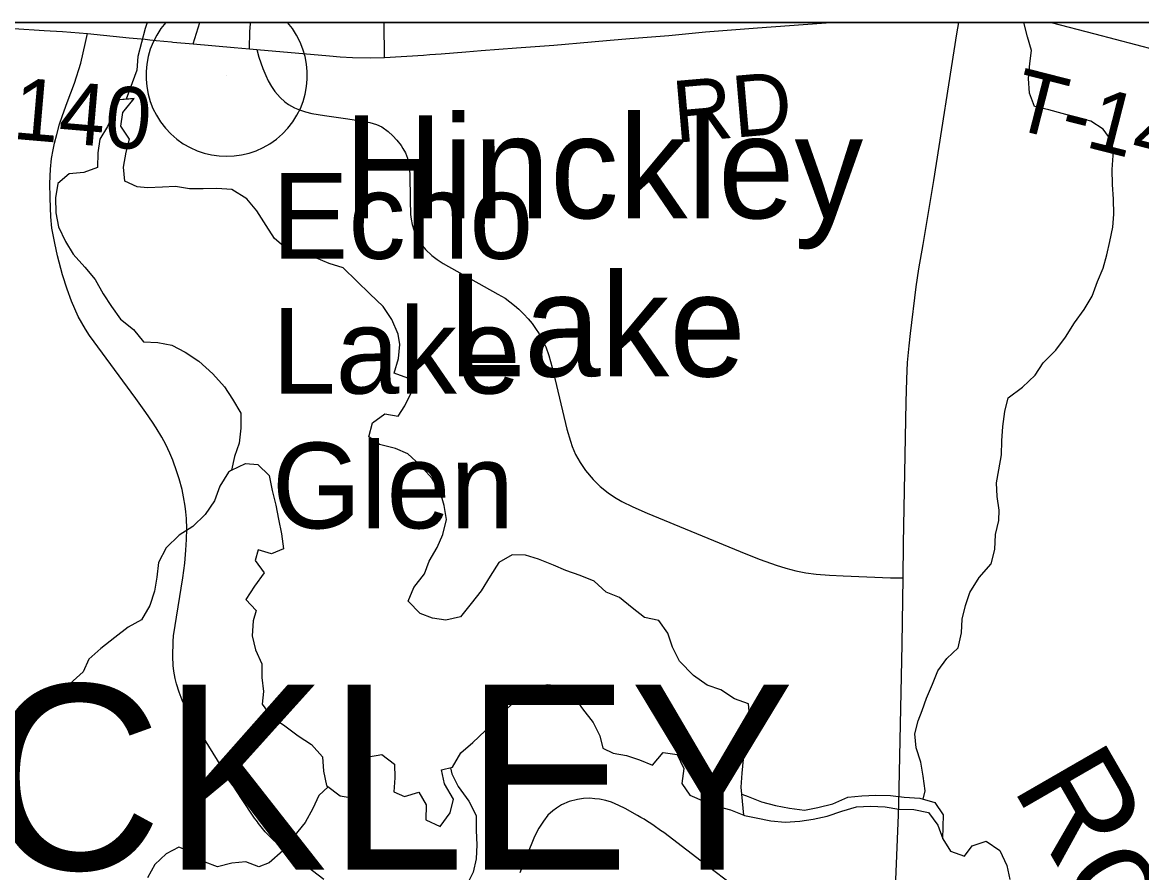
# Model space of a CAD drawing. Extents: x 0 to 34, y 0 to 22.
# Drawn here: x 6.095 to 7.127, y 20.117 to 20.9 of the extents above; entities that cross this region are included whole.
import ezdxf

# ---------------------------------------------------------------- set-up
doc = ezdxf.new("R2010")
doc.units = 0
for name, color, linetype in [('GM_X_Corporation', 7, 'Continuous'), ('GM_X_County_Road', 7, 'Continuous'), ('GM_X_County_Road_Text', 7, 'Continuous'), ('GM_X_Major_Lake', 7, 'Continuous'), ('GM_X_Major_Lake_Text', 7, 'Continuous'), ('GM_X_Minor_River', 7, 'Continuous'), ('GM_X_Minor_River_Text', 7, 'Continuous'), ('GM_X_State_Shield', 7, 'Continuous'), ('GM_X_Township_Road', 7, 'Continuous'), ('GM_X_Township_Road_Text', 7, 'Continuous'), ('GM_X_Township_Text', 7, 'Continuous'), ('GM_X_Unincorporated_Location', 7, 'Continuous'), ('GM_X_Unincorporated_Text', 7, 'Continuous'), ('SH_Data', 7, 'Continuous')]:
    doc.layers.add(name, color=color, linetype=linetype)

msp = doc.modelspace()

# ---------------------------------------------------------------- linework, layer by layer
at = {"layer": 'GM_X_Corporation'}
msp.add_lwpolyline([(7.991, 17.7727), (7.9901, 18.1613), (7.988, 19.001), (7.9884, 19.0254), (7.9898, 19.1149), (7.9901, 19.6615), (7.9904, 20.2824), (7.9906, 20.6512), (7.9922, 20.9), (2.1, 20.9), (2.1, 14.1)], dxfattribs=at)
msp.add_lwpolyline([(7.9922, 20.9), (2.8099, 20.9), (2.8107, 20.774), (2.8158, 19.9868), (2.8247, 19.0323), (3.279, 19.0395), (3.3208, 19.0402), (3.8964, 19.0508), (4.1999, 19.0575), (4.5008, 19.0629), (4.7704, 19.0672), (4.9094, 19.0728), (5.4081, 19.0763), (6.7986, 19.0964), (7.9898, 19.1149), (7.9901, 19.6615), (7.9904, 20.2824), (7.9906, 20.6512)], close=True, dxfattribs=at)
at = {"layer": 'GM_X_County_Road'}
for points in [[(5.9874, 20.8999), (6.0214, 20.8978), (6.0292, 20.8975), (6.0736, 20.8949), (6.0871, 20.8943), (6.1153, 20.8926), (6.1321, 20.8917), (6.155, 20.8899), (6.1936, 20.8859)], [(6.2326, 20.882), (6.2337, 20.8819), (6.2524, 20.8803), (6.2902, 20.8768), (6.3044, 20.8756), (6.3111, 20.8749), (6.3781, 20.8691), (6.3879, 20.8684), (6.3995, 20.8678), (6.416, 20.8674), (6.429, 20.8677), (6.4649, 20.8699), (6.4707, 20.8703), (6.4811, 20.871), (6.5039, 20.873), (6.5179, 20.8741), (6.5507, 20.8766), (6.585, 20.8789), (6.6197, 20.8821), (6.6369, 20.8836), (6.6552, 20.8851), (6.6709, 20.8864), (6.691, 20.888), (6.7248, 20.8912), (6.7729, 20.8949), (6.8318, 20.8993), (6.8403, 20.9)], [(6.9003, 20.1099), (6.9027, 20.1697), (6.9031, 20.1793), (6.9062, 20.3272), (6.907, 20.3883), (6.9073, 20.4197), (6.9097, 20.55), (6.9103, 20.5711), (6.911, 20.5866), (6.9125, 20.6021), (6.9138, 20.6133), (6.9191, 20.6562), (6.9216, 20.673), (6.9254, 20.6953), (6.9352, 20.7542), (6.9566, 20.8895), (6.9584, 20.9)], [(6.1936, 20.8859), (6.2084, 20.8844), (6.2125, 20.884), (6.2184, 20.8834), (6.2326, 20.882)]]:
    msp.add_lwpolyline(points, dxfattribs=at)
at = {"layer": 'GM_X_Major_Lake'}
for points in [[(6.1981, 20.8298), (6.1842, 20.8287), (6.1793, 20.8162), (6.1737, 20.804), (6.1665, 20.7925), (6.1647, 20.7799), (6.1644, 20.7662), (6.1518, 20.7616), (6.1381, 20.7604), (6.1279, 20.7516), (6.1257, 20.7383), (6.1258, 20.7246), (6.1285, 20.7117), (6.1347, 20.698), (6.1419, 20.6863), (6.1527, 20.6745), (6.1622, 20.6632), (6.1695, 20.6499), (6.1772, 20.6381), (6.1856, 20.6264), (6.1975, 20.6169), (6.2067, 20.6056), (6.22, 20.6049), (6.2329, 20.6026), (6.2451, 20.5962), (6.2577, 20.5879), (6.2707, 20.5762), (6.2814, 20.5641), (6.2887, 20.5527), (6.2964, 20.5398), (6.2965, 20.5261), (6.295, 20.5124), (6.2905, 20.4999), (6.2879, 20.4873), (6.3008, 20.4934), (6.3122, 20.4927), (6.3226, 20.4825), (6.3253, 20.4688), (6.3288, 20.4552), (6.3311, 20.4422), (6.3339, 20.4286), (6.3359, 20.4149), (6.3248, 20.4103), (6.3126, 20.414), (6.3097, 20.4041), (6.3181, 20.3927), (6.309, 20.3805), (6.3011, 20.3683), (6.3106, 20.3581), (6.3077, 20.3486), (6.307, 20.3349), (6.3101, 20.3219), (6.3158, 20.309), (6.3159, 20.2965), (6.3175, 20.2836), (6.316, 20.2718), (6.3245, 20.2604), (6.3371, 20.2517), (6.3493, 20.2426), (6.3615, 20.2347), (6.3718, 20.2234), (6.3727, 20.21), (6.3754, 20.1967), (6.388, 20.1873), (6.4013, 20.1851), (6.4035, 20.1988), (6.4046, 20.2125), (6.4141, 20.2232), (6.4266, 20.2255), (6.4381, 20.2165), (6.4385, 20.2039), (6.4374, 20.191), (6.4474, 20.1868), (6.4606, 20.1907), (6.4672, 20.1789), (6.4669, 20.1652), (6.4802, 20.1592), (6.4893, 20.1718), (6.4926, 20.1844), (6.4842, 20.1984), (6.4815, 20.2113), (6.4917, 20.2137), (6.4993, 20.227), (6.5103, 20.2366), (6.5216, 20.2473), (6.533, 20.2599), (6.5451, 20.2706), (6.5545, 20.2828), (6.5675, 20.2882), (6.5796, 20.2898), (6.5918, 20.2883), (6.6033, 20.2789), (6.6113, 20.2675), (6.6213, 20.255), (6.6274, 20.2425)], [(6.1977, 20.8297), (6.1842, 20.8287), (6.1793, 20.8162), (6.1737, 20.804), (6.1665, 20.7925), (6.1647, 20.7799), (6.1644, 20.7662), (6.1518, 20.7616), (6.1381, 20.7604), (6.1279, 20.7516), (6.1257, 20.7383), (6.1258, 20.7246), (6.1285, 20.7117), (6.1347, 20.698), (6.1419, 20.6863), (6.1527, 20.6745), (6.1622, 20.6632), (6.1695, 20.6499), (6.1772, 20.6381), (6.1856, 20.6264), (6.1975, 20.6169), (6.2067, 20.6056), (6.22, 20.6049), (6.2329, 20.6026), (6.2451, 20.5962), (6.2577, 20.5879), (6.2707, 20.5762), (6.2814, 20.5641), (6.2887, 20.5527), (6.2964, 20.5398), (6.2965, 20.5261), (6.295, 20.5124), (6.2905, 20.4999), (6.2879, 20.4873), (6.3008, 20.4934), (6.3122, 20.4927), (6.3226, 20.4825), (6.3253, 20.4688), (6.3288, 20.4552), (6.3311, 20.4422), (6.3339, 20.4286), (6.3359, 20.4149), (6.3248, 20.4103), (6.3126, 20.414), (6.3097, 20.4041), (6.3181, 20.3927), (6.309, 20.3805), (6.3011, 20.3683), (6.3106, 20.3581), (6.3077, 20.3486), (6.307, 20.3349), (6.3101, 20.3219), (6.3158, 20.309), (6.3159, 20.2965), (6.3175, 20.2836), (6.316, 20.2718), (6.3245, 20.2604), (6.3371, 20.2517), (6.3493, 20.2426), (6.3615, 20.2347), (6.3718, 20.2234), (6.3727, 20.21), (6.3754, 20.1967), (6.388, 20.1873), (6.4013, 20.1851), (6.4035, 20.1988), (6.4046, 20.2125), (6.4141, 20.2232), (6.4266, 20.2255), (6.4381, 20.2165), (6.4385, 20.2039), (6.4374, 20.191), (6.4474, 20.1868), (6.4606, 20.1907), (6.4672, 20.1789), (6.4669, 20.1652), (6.4802, 20.1592), (6.4893, 20.1718), (6.4926, 20.1844), (6.4842, 20.1984), (6.4815, 20.2113), (6.4917, 20.2137), (6.4993, 20.227), (6.5103, 20.2366), (6.5216, 20.2473), (6.533, 20.2599), (6.5451, 20.2706), (6.5545, 20.2828), (6.5675, 20.2882), (6.5796, 20.2898), (6.5918, 20.2883), (6.6033, 20.2789), (6.6113, 20.2675), (6.6213, 20.255), (6.6274, 20.2425)], [(6.1859, 20.8044), (6.1877, 20.817), (6.1981, 20.8298)], [(6.1859, 20.8044), (6.1877, 20.817), (6.1979, 20.8296)], [(6.6274, 20.2425), (6.6301, 20.2311), (6.6397, 20.2266), (6.6519, 20.2244), (6.6641, 20.2206), (6.6759, 20.2157), (6.6857, 20.2272), (6.6987, 20.2254), (6.7048, 20.2125), (6.703, 20.1988), (6.7103, 20.1878), (6.724, 20.1821), (6.7362, 20.1776), (6.748, 20.1743), (6.7602, 20.1694), (6.759, 20.1823), (6.7578, 20.1952), (6.7585, 20.2082), (6.7599, 20.2211), (6.7595, 20.2336), (6.7617, 20.2466), (6.7658, 20.2588), (6.7646, 20.2721), (6.7517, 20.2766), (6.7391, 20.2849), (6.7265, 20.2894), (6.7139, 20.2981), (6.7009, 20.3113), (6.6944, 20.3242), (6.6901, 20.3371), (6.6817, 20.3489), (6.6687, 20.3515), (6.6573, 20.3606), (6.6454, 20.37), (6.6332, 20.3749), (6.6221, 20.3851), (6.6092, 20.3904), (6.5962, 20.3949), (6.5848, 20.3998), (6.571, 20.4054), (6.5588, 20.4091), (6.5467, 20.4095), (6.5342, 20.4022), (6.5262, 20.3896), (6.5179, 20.3762), (6.5089, 20.3644), (6.499, 20.3522), (6.4853, 20.3491), (6.4732, 20.3509), (6.4617, 20.3554), (6.4506, 20.3668), (6.4559, 20.3793), (6.4657, 20.3919), (6.4702, 20.4034), (6.4774, 20.416), (6.4827, 20.4282), (6.486, 20.4419), (6.484, 20.4548), (6.4802, 20.4677), (6.4729, 20.4798), (6.4618, 20.492), (6.4503, 20.5025), (6.4389, 20.5074), (6.4244, 20.5112), (6.4145, 20.518), (6.4178, 20.5309), (6.4292, 20.5393), (6.4414, 20.5371), (6.4478, 20.5467), (6.4538, 20.5592), (6.4503, 20.5722), (6.4378, 20.5767), (6.4419, 20.5904), (6.443, 20.6033), (6.4414, 20.6128), (6.4356, 20.6261), (6.4276, 20.6382), (6.4153, 20.65), (6.4035, 20.6617), (6.3909, 20.6738), (6.3779, 20.6779), (6.3661, 20.6828), (6.3531, 20.6873), (6.3398, 20.6903), (6.3276, 20.7009), (6.3199, 20.713), (6.3111, 20.7263), (6.3019, 20.7373), (6.2881, 20.7459), (6.2744, 20.747), (6.2619, 20.7466), (6.2493, 20.7465), (6.2364, 20.7487), (6.2242, 20.7483), (6.2105, 20.7475), (6.201, 20.7486), (6.1895, 20.7538), (6.1883, 20.7667), (6.1909, 20.7805), (6.1939, 20.7923), (6.1859, 20.8044)]]:
    msp.add_lwpolyline(points, dxfattribs=at)
at = {"layer": 'GM_X_Minor_River'}
for points in [[(6.2102, 20.9), (6.2084, 20.8945), (6.2016, 20.8686), (6.2005, 20.8561), (6.1909, 20.8293)], [(6.9256, 20.1844), (6.9274, 20.1918), (6.9255, 20.2055), (6.9232, 20.2184), (6.919, 20.2314), (6.9178, 20.2443), (6.9208, 20.2565), (6.9246, 20.266), (6.9284, 20.2774), (6.9341, 20.2903), (6.939, 20.3025), (6.9474, 20.3139), (6.9577, 20.3238), (6.9607, 20.3375), (6.9614, 20.3501), (6.9645, 20.3626), (6.9686, 20.3748), (6.977, 20.3885), (6.988, 20.4011), (6.9914, 20.4144), (6.9921, 20.4281), (6.9952, 20.441), (6.9955, 20.4505), (6.9936, 20.4631), (6.9932, 20.4756), (6.9951, 20.4878), (6.9977, 20.5015), (6.9981, 20.5144), (6.9988, 20.5277), (7.0007, 20.5414), (7.0037, 20.554), (7.0171, 20.5639), (7.0288, 20.5749), (7.036, 20.5863), (7.0478, 20.5981), (7.0566, 20.6099), (7.0649, 20.6233), (7.074, 20.6354), (7.0812, 20.6476), (7.0862, 20.6613), (7.0915, 20.6735), (7.0949, 20.6857), (7.0975, 20.6982), (7.1002, 20.7112), (7.1013, 20.7233), (7.1009, 20.737), (7.1001, 20.7507), (7.0997, 20.7644), (7.1005, 20.7773), (7.0997, 20.7903), (7.0913, 20.8017), (7.0799, 20.8089), (7.0662, 20.8127), (7.0536, 20.8161), (7.0414, 20.8195), (7.0281, 20.8225), (7.0235, 20.8347), (7.0227, 20.8484), (7.0238, 20.862), (7.0254, 20.8742), (7.0215, 20.8868), (7.0184, 20.9)], [(6.2879, 20.4873), (6.2851, 20.4857), (6.2771, 20.4728), (6.2722, 20.4591), (6.2635, 20.4465), (6.2521, 20.4355), (6.2395, 20.4275), (6.2277, 20.4157), (6.2205, 20.4024), (6.219, 20.3887), (6.2168, 20.3758), (6.2126, 20.3628), (6.205, 20.3495), (6.1925, 20.3426), (6.1803, 20.3331), (6.1674, 20.3232), (6.1563, 20.3133), (6.151, 20.3015), (6.1389, 20.2905), (6.1263, 20.2832), (6.1134, 20.2756)], [(6.4897, 20.2132), (6.491, 20.2076), (6.4967, 20.1958), (6.5066, 20.1825), (6.5135, 20.1692), (6.5135, 20.1555), (6.5139, 20.1422), (6.5135, 20.1293), (6.5105, 20.1171), (6.5048, 20.1053)], [(6.3769, 20.1956), (6.3685, 20.1877), (6.3628, 20.1755), (6.3559, 20.1626), (6.3449, 20.1496), (6.3351, 20.1367), (6.3225, 20.1256), (6.313, 20.1218), (6.3012, 20.1264), (6.2883, 20.1252), (6.275, 20.1218), (6.2635, 20.1263), (6.251, 20.1354), (6.2392, 20.14), (6.2278, 20.1339), (6.2171, 20.124), (6.2103, 20.1118)], [(6.7584, 20.1888), (6.7642, 20.1867), (6.7764, 20.1817), (6.7893, 20.1783), (6.8023, 20.1761), (6.816, 20.1742), (6.8285, 20.1765), (6.8422, 20.1799), (6.8559, 20.186), (6.8688, 20.1872), (6.8818, 20.188), (6.8955, 20.1876), (6.908, 20.1861), (6.9225, 20.1853), (6.9362, 20.1812), (6.9438, 20.1698), (6.9434, 20.1476)], [(6.7601, 20.1694), (6.7608, 20.1691), (6.7714, 20.1669), (6.7851, 20.1643), (6.7981, 20.1631), (6.8118, 20.1639), (6.824, 20.1658), (6.8369, 20.1685), (6.8506, 20.1731), (6.8639, 20.1773), (6.8768, 20.1777), (6.8905, 20.1773), (6.9031, 20.1751), (6.9168, 20.1747), (6.9305, 20.172), (6.9389, 20.1603), (6.9435, 20.1477), (6.9507, 20.1363), (6.9636, 20.1318), (6.9705, 20.1413), (6.9834, 20.1455), (6.996, 20.1368), (7.0025, 20.1231), (7.0055, 20.1102)]]:
    msp.add_lwpolyline(points, dxfattribs=at)
at = {"layer": 'GM_X_State_Shield'}
msp.add_line((6.3394, 20.9), (6.2274, 20.9), dxfattribs=at)
msp.add_arc((6.2834, 20.851), 0.0744, 138.7805, 41.2195, dxfattribs=at)
at = {"layer": 'GM_X_Township_Road'}
for p, q in [((6.2524, 20.8803), (6.2587, 20.9)), ((6.429, 20.8677), (6.4286, 20.9))]:
    msp.add_line(p, q, dxfattribs=at)
for points in [[(6.3044, 20.8756), (6.3048, 20.8917), (6.3054, 20.8987), (6.3056, 20.9)], [(7.0434, 20.9), (7.0836, 20.8896), (7.1399, 20.8748), (7.1727, 20.8663), (7.2055, 20.8576), (7.2387, 20.8489), (7.272, 20.8404), (7.3043, 20.8317), (7.3222, 20.8268), (7.3507, 20.8194), (7.3747, 20.813), (7.3906, 20.8088), (7.4016, 20.806), (7.4263, 20.7995), (7.4799, 20.7846), (7.4973, 20.7796), (7.5199, 20.7727), (7.5373, 20.7673), (7.5561, 20.7615), (7.5753, 20.7553), (7.626, 20.7391)], [(6.3729, 20.1103), (6.3364, 20.1383), (6.3348, 20.1395), (6.3333, 20.1407), (6.3318, 20.1419), (6.3303, 20.1432), (6.3288, 20.1445), (6.3273, 20.1458), (6.3259, 20.1471), (6.3245, 20.1485), (6.3231, 20.1499), (6.3217, 20.1513), (6.3204, 20.1527), (6.319, 20.1542), (6.3177, 20.1557), (6.3165, 20.1572), (6.3152, 20.1587), (6.314, 20.1602), (6.3128, 20.1618), (6.3117, 20.1634), (6.3106, 20.165), (6.309, 20.1667), (6.3067, 20.1703), (6.2919, 20.193), (6.2501, 20.2604), (6.2459, 20.2682), (6.2423, 20.2755), (6.2395, 20.2828), (6.2371, 20.2905), (6.2359, 20.2955), (6.2346, 20.3022), (6.234, 20.3073), (6.2337, 20.3157), (6.234, 20.3294), (6.2345, 20.3346), (6.2431, 20.3883), (6.2449, 20.4018), (6.2459, 20.4136), (6.2463, 20.4234), (6.2466, 20.4332), (6.2463, 20.4429), (6.2459, 20.449), (6.2451, 20.4541), (6.2435, 20.4627), (6.2423, 20.4696), (6.2396, 20.4794), (6.2376, 20.4859), (6.2337, 20.4965), (6.2309, 20.5032), (6.2273, 20.5112), (6.2237, 20.5177), (6.2184, 20.5263), (6.215, 20.5317), (6.2089, 20.5406), (6.1996, 20.5534), (6.1569, 20.6114), (6.1534, 20.6172), (6.1466, 20.6289), (6.1405, 20.643), (6.1363, 20.6543), (6.1321, 20.6674), (6.1276, 20.6848), (6.1249, 20.6967), (6.1224, 20.7105), (6.1213, 20.7207), (6.1209, 20.7292), (6.1207, 20.7386), (6.1204, 20.7515), (6.1209, 20.7649), (6.1221, 20.7746), (6.1235, 20.7827), (6.1248, 20.7886), (6.1268, 20.7966), (6.1293, 20.8061), (6.1321, 20.8143), (6.1364, 20.8263), (6.143, 20.844), (6.1491, 20.8625), (6.1534, 20.8815), (6.155, 20.8899)], [(6.3111, 20.8749), (6.3131, 20.8681), (6.3168, 20.8576), (6.3194, 20.8511), (6.3216, 20.8461), (6.3247, 20.8409), (6.3279, 20.8363), (6.3327, 20.8308), (6.3369, 20.8267), (6.3405, 20.8243), (6.3458, 20.8214), (6.3506, 20.8194), (6.3561, 20.8175), (6.362, 20.8162), (6.3736, 20.8142), (6.3951, 20.811), (6.4089, 20.809), (6.4154, 20.8077), (6.4214, 20.8059), (6.4264, 20.8037), (6.4322, 20.7996), (6.4366, 20.7954), (6.4403, 20.7915), (6.4442, 20.7867), (6.4459, 20.7839), (6.4482, 20.7797), (6.4501, 20.7749), (6.4514, 20.769), (6.4523, 20.7605), (6.4526, 20.7361), (6.453, 20.723), (6.4536, 20.7186), (6.4545, 20.7139), (6.456, 20.7088), (6.4584, 20.7034), (6.4619, 20.6971), (6.4639, 20.694), (6.4667, 20.6907), (6.4724, 20.6851), (6.4774, 20.6814), (6.4829, 20.6779), (6.5333, 20.6497), (6.54, 20.6458), (6.5486, 20.6392), (6.5526, 20.6357), (6.5573, 20.6311), (6.5613, 20.6267), (6.5649, 20.6224), (6.5682, 20.6178), (6.5715, 20.613), (6.5747, 20.6072), (6.5776, 20.6011), (6.5804, 20.593), (6.5834, 20.5821), (6.5874, 20.5653), (6.597, 20.5253), (6.6003, 20.514), (6.6018, 20.5092), (6.6051, 20.5018), (6.6092, 20.4946), (6.6142, 20.4871), (6.6212, 20.4788), (6.6278, 20.4723), (6.635, 20.4664), (6.6409, 20.4625), (6.6476, 20.4586), (6.6578, 20.4536), (6.671, 20.4479), (6.762, 20.4102), (6.7753, 20.4051), (6.7899, 20.3999), (6.799, 20.3972), (6.808, 20.3946), (6.8174, 20.3927), (6.8267, 20.3916), (6.839, 20.3907), (6.8518, 20.39), (6.8955, 20.3883), (6.907, 20.3883)], [(6.7474, 20.1067), (6.7288, 20.1209), (6.6863, 20.1534), (6.6834, 20.1555), (6.6775, 20.1597), (6.6744, 20.1618), (6.6714, 20.1637), (6.6683, 20.1657), (6.6652, 20.1675), (6.6621, 20.1693), (6.6507, 20.1756), (6.6449, 20.1784), (6.6383, 20.1814), (6.6329, 20.1829), (6.6271, 20.1842), (6.6228, 20.1847), (6.6181, 20.1851), (6.6123, 20.1849), (6.6067, 20.1839), (6.5992, 20.182), (6.5922, 20.179), (6.5875, 20.1761), (6.5841, 20.1734), (6.5796, 20.1694), (6.5755, 20.1641), (6.5713, 20.1575), (6.5673, 20.1497), (6.5536, 20.1164)]]:
    msp.add_lwpolyline(points, dxfattribs=at)
at = {"layer": 'GM_X_Unincorporated_Location'}
msp.add_line((6.2834, 20.851), (6.2834, 20.851), dxfattribs=at)
at = {"layer": 'SH_Data'}
msp.add_line((2.1, 20.9), (8.9, 20.9), dxfattribs=at)

# ---------------------------------------------------------------- texts
at = {"layer": 'GM_X_County_Road_Text'}
for s, rotation, p in [('C-140', 355.1012, (6.0053, 20.7997)), ('RD', 4.969, (6.6971, 20.789))]:
    msp.add_text(s, height=0.05682, rotation=rotation, dxfattribs=at).set_placement(p)
at = {"layer": 'GM_X_Major_Lake_Text'}
for s, rotation, p in [('Hinckley', 359.9828, (6.3914, 20.7196)), ('Lake', 359.9829, (6.4872, 20.5738))]:
    msp.add_text(s, height=0.09474, rotation=rotation, dxfattribs=at).set_placement(p)
at = {"layer": 'GM_X_Minor_River_Text'}
msp.add_text('Rocky', height=0.09474, rotation=299.9806, dxfattribs=at).set_placement((7.007, 20.1954))
at = {"layer": 'GM_X_Township_Road_Text'}
msp.add_text('T-140', height=0.05682, rotation=345.6951, dxfattribs=at).set_placement((7.0042, 20.8033))
at = {"layer": 'GM_X_Township_Text'}
msp.add_text('HINCKLEY', height=0.17045, rotation=0, dxfattribs=at).set_placement((5.667, 20.1193))
at = {"layer": 'GM_X_Unincorporated_Text'}
for s, p in [('Echo', (6.3252, 20.6822)), ('Lake', (6.3252, 20.558)), ('Glen', (6.3252, 20.4338))]:
    msp.add_text(s, height=0.07898, rotation=0, dxfattribs=at).set_placement(p)

doc.saveas('drawing.dxf')
